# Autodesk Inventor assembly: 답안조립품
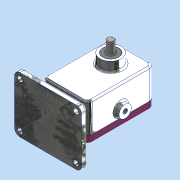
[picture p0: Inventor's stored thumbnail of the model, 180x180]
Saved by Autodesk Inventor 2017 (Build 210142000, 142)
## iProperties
Part Number: 답안조립품
Material: 일반
Document SubType Name: Assembly
Designer: MRC
Author: MRC
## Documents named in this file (11)
- C:\Users\MRC\Desktop\700407V1048\답안조립품.iam
- C:\Users\MRC\Desktop\700407V1048\본체.ipt
- C:\Users\MRC\Desktop\700407V1048\개스킷.ipt
- C:\Users\MRC\Desktop\700407V1048\메인축.ipt
- C:\Users\MRC\Desktop\700407V1048\베어링부시.ipt
- C:\Users\MRC\Desktop\700407V1048\볼트 M5.ipt
- C:\Users\MRC\Desktop\700407V1048\서브축.ipt
- C:\Users\MRC\Desktop\700407V1048\스퍼기어.ipt
- C:\Users\MRC\Desktop\700407V1048\오일 실 16 28 7.ipt
- C:\Users\MRC\Desktop\700407V1048\커버.ipt
- C:\Users\MRC\Desktop\700407V1048\키 6 x 6 x 18.ipt
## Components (1 placed, 1 different names)
1. 개스킷:1
